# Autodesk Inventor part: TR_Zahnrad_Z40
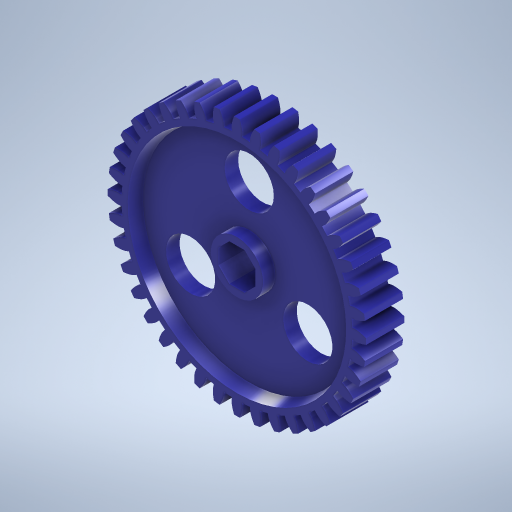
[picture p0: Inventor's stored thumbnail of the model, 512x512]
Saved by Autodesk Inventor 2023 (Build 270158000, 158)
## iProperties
Created: 2023-11
Part Number: TR_Zahnrad_Z40
Material: Generic
Document SubType Name: Modeling
Designer: AdminForWorker
Density: 1 g/cm^3
Appearance: Default
Title: Component1
Author: AdminForWorker
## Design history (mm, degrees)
feature "Body1"
workplane "Arbeitsebene1"
sketch "Skizze1"
  geometry: C1 r 17.25 at (-18.518, 8.045); C2 r 4.25 at (-18.518, 8.045); 1 further point
  constraints: 2 centre point, 2 coincident
  dimensions: "d0" = 34.5 diameter of C1; "d1" = 8.5 diameter of C2
extrude "Extrusion1" cut sketch "Skizze1" distance "d2" = 2; taper "d3" = 0 deg
mirror "Spiegeln1"
chamfer "Fase1" distance "d4" = 0.5; stored, may be unused: second distance "d5" = 2, angle "d6" = 45 deg
chamfer "Fase2" distance "d18" = 0.5; stored, may be unused: second distance "d19" = 2, angle "d20" = 45 deg
sketch "Skizze2"
  geometry: L1 (1.243, -3)-(-1.243, -3); L2 (-1.243, -3)-(-3, -1.243); L3 (-3, -1.243)-(-3, 1.243); L4 (-3, 1.243)-(-1.243, 3); L5 (-1.243, 3)-(1.243, 3); L6 (1.243, 3)-(3, 1.243); L7 (3, 1.243)-(3, -1.243); L8 (3, -1.243)-(1.243, -3); C1 r 4.25 at (0, 0) reference; 2 further points
  constraints: 16 end point, 1 coincident, 1 horizontal, 17 other
  dimensions: "d8" = 6 distance between parallel lines of L7 L3 (= AchteckUmkreis)
extrude "Extrusion2" cut sketch "Skizze2" extent not by distance; stored distance "d9" = 0; taper "d10" = 0 deg
sketch "Skizze3"
  geometry: C1 r 4 at (0, 11); 1 further point
  constraints: 1 centre point, 1 vertical alignment
  dimensions: "d11" = 8 diameter of C1; "d12" = 11 distance of point (0, 0) C1.centre
extrude "Extrusion3" cut sketch "Skizze3" extent not by distance; stored distance "d13" = 0; taper "d14" = 0 deg
pattern_circular "Runde Anordnung1" dims angle "d16" = 360 deg
body "Solid1"
other parameters: "Radius" = 2.075 [user parameter], "Fasen" = 0.5 [user parameter], "Dicke" = 0.8 [user parameter], "Breitloch" = 2 [user parameter], "Langloch" = 32 [user parameter], "AchteckUmkreis" = 6 [user parameter; used in 1 equation term], "DAchsAufnahme" = 4.1 [user parameter], "AchsDurchmesser" = 4 [user parameter], "AchsFase" = 0.5 [user parameter]
